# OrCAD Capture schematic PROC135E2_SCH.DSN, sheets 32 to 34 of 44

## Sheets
32 32. USER EXPANSION CONNECTOR: size C; title: USER EXPANSION CONNECTOR
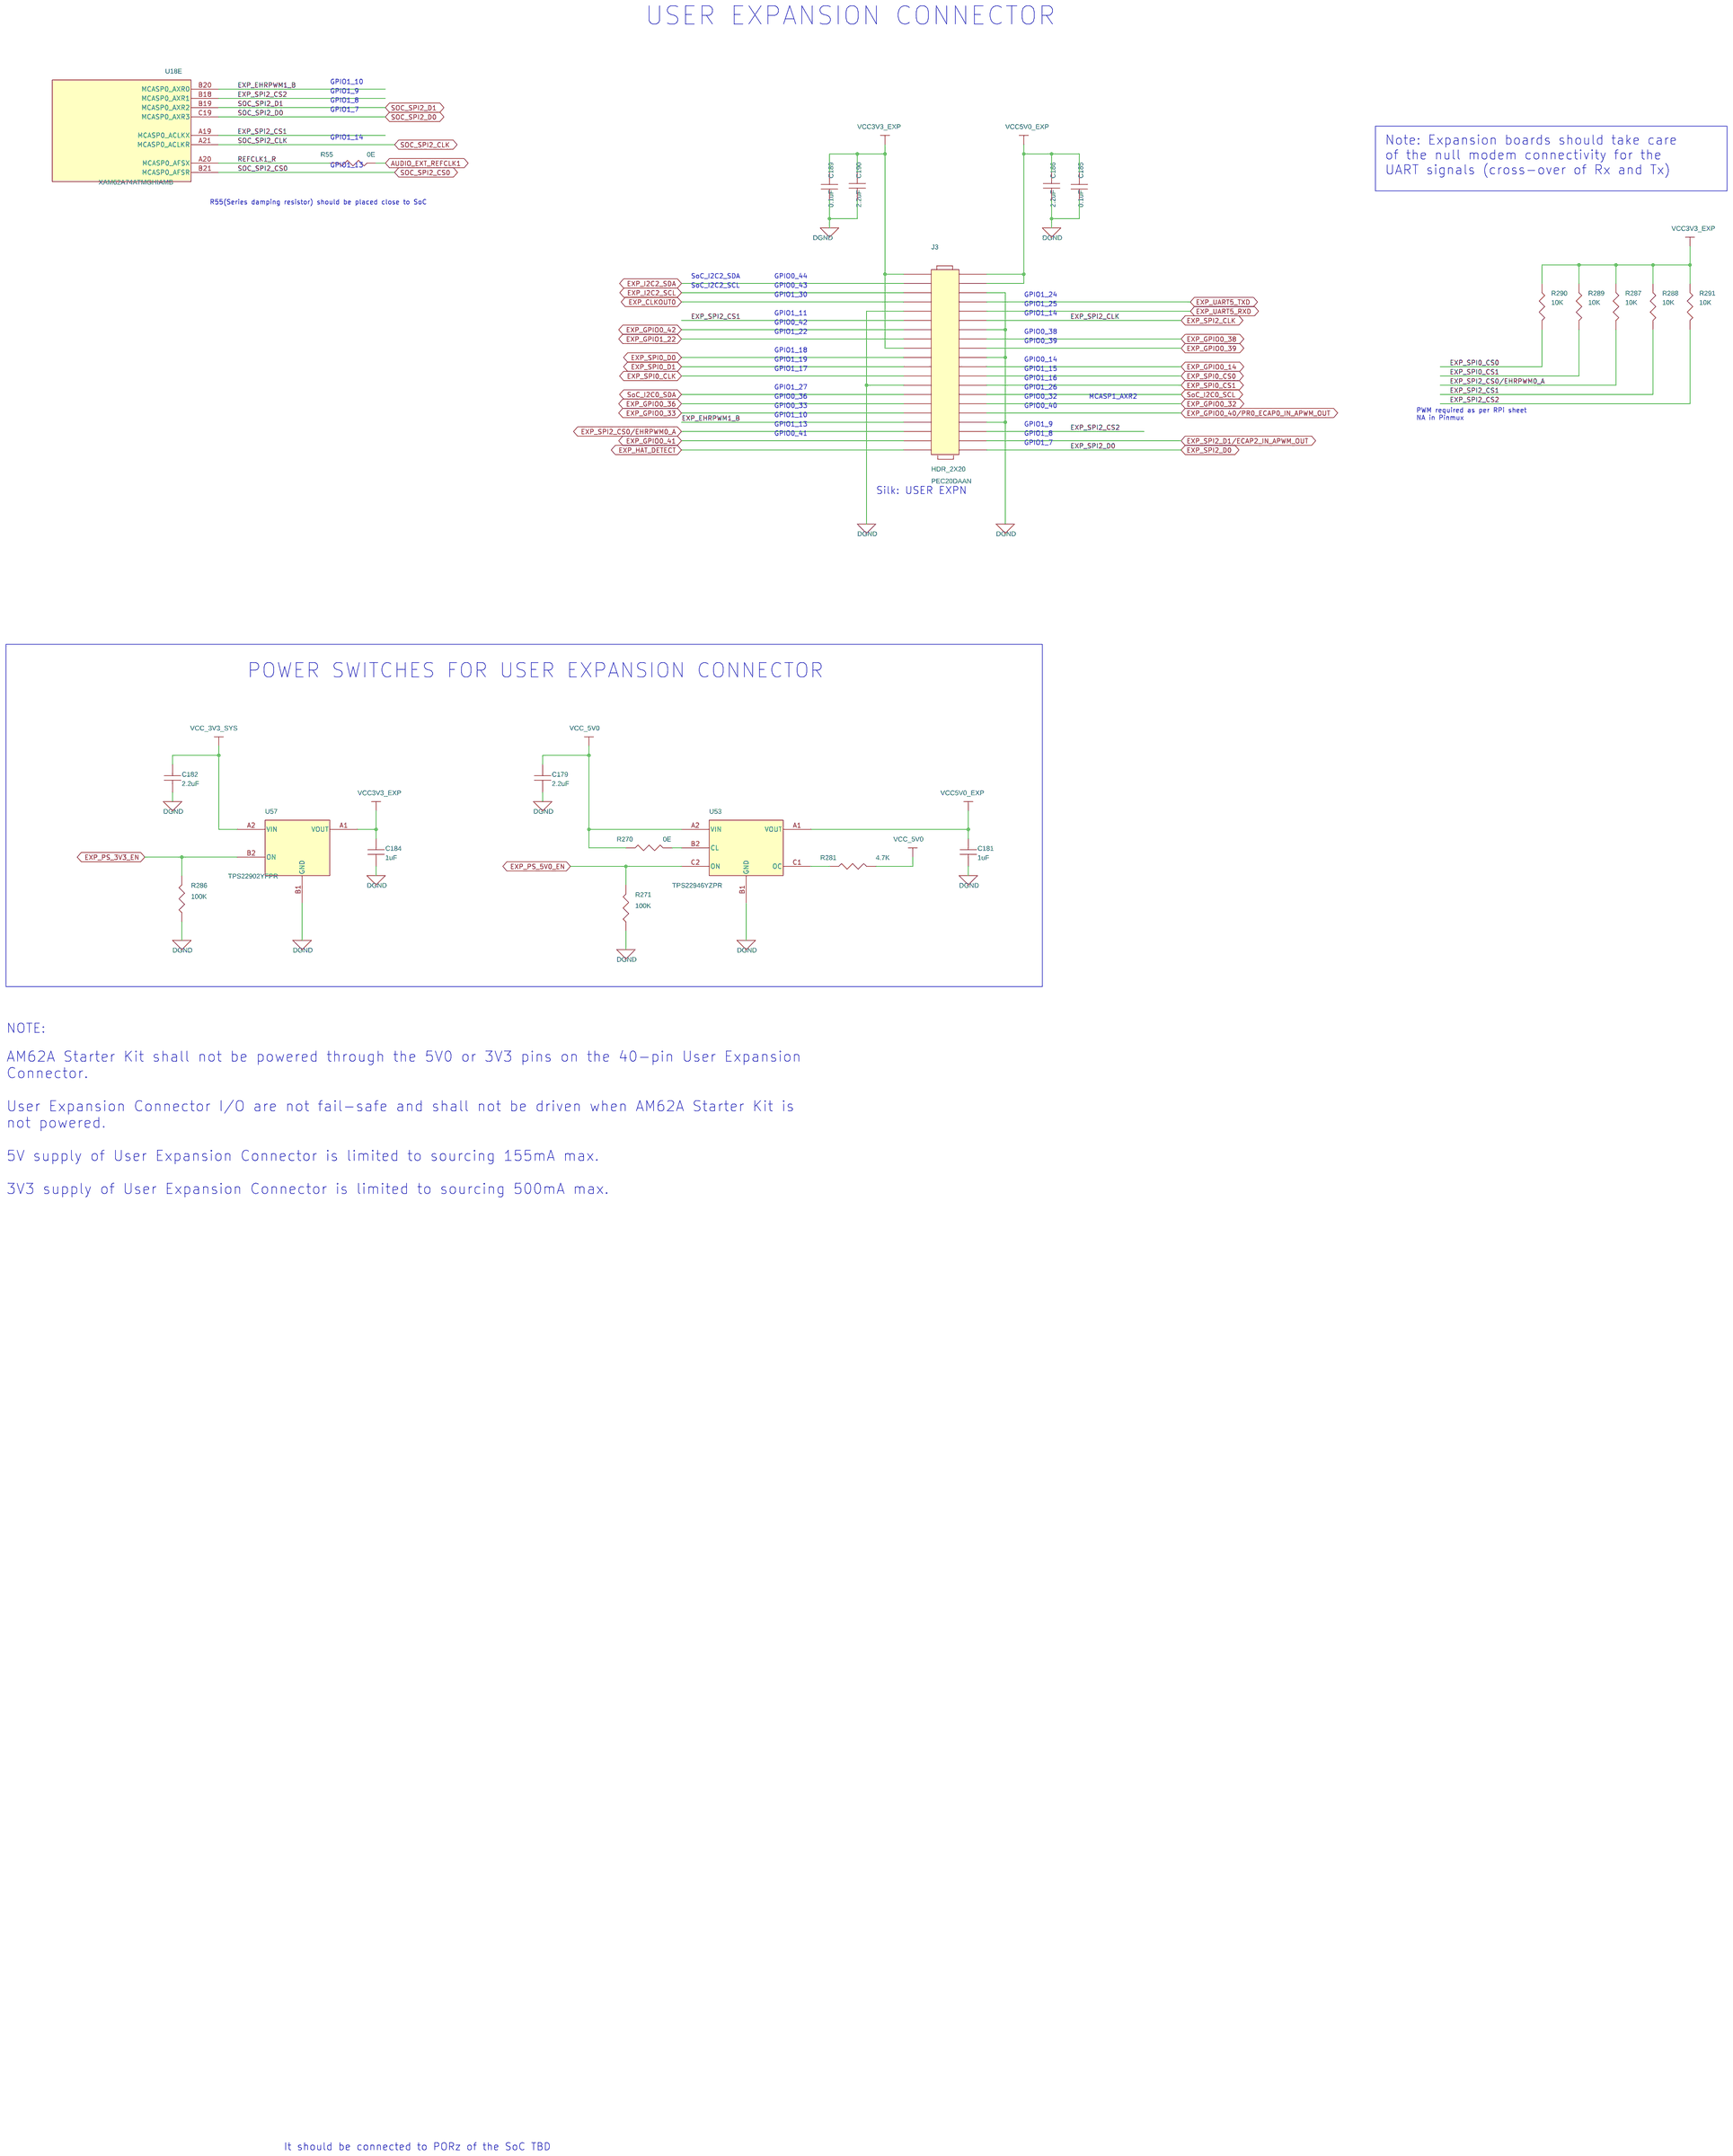
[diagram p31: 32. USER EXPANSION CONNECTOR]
33 33. MCU HEADER: size C; title: MCU HEADER
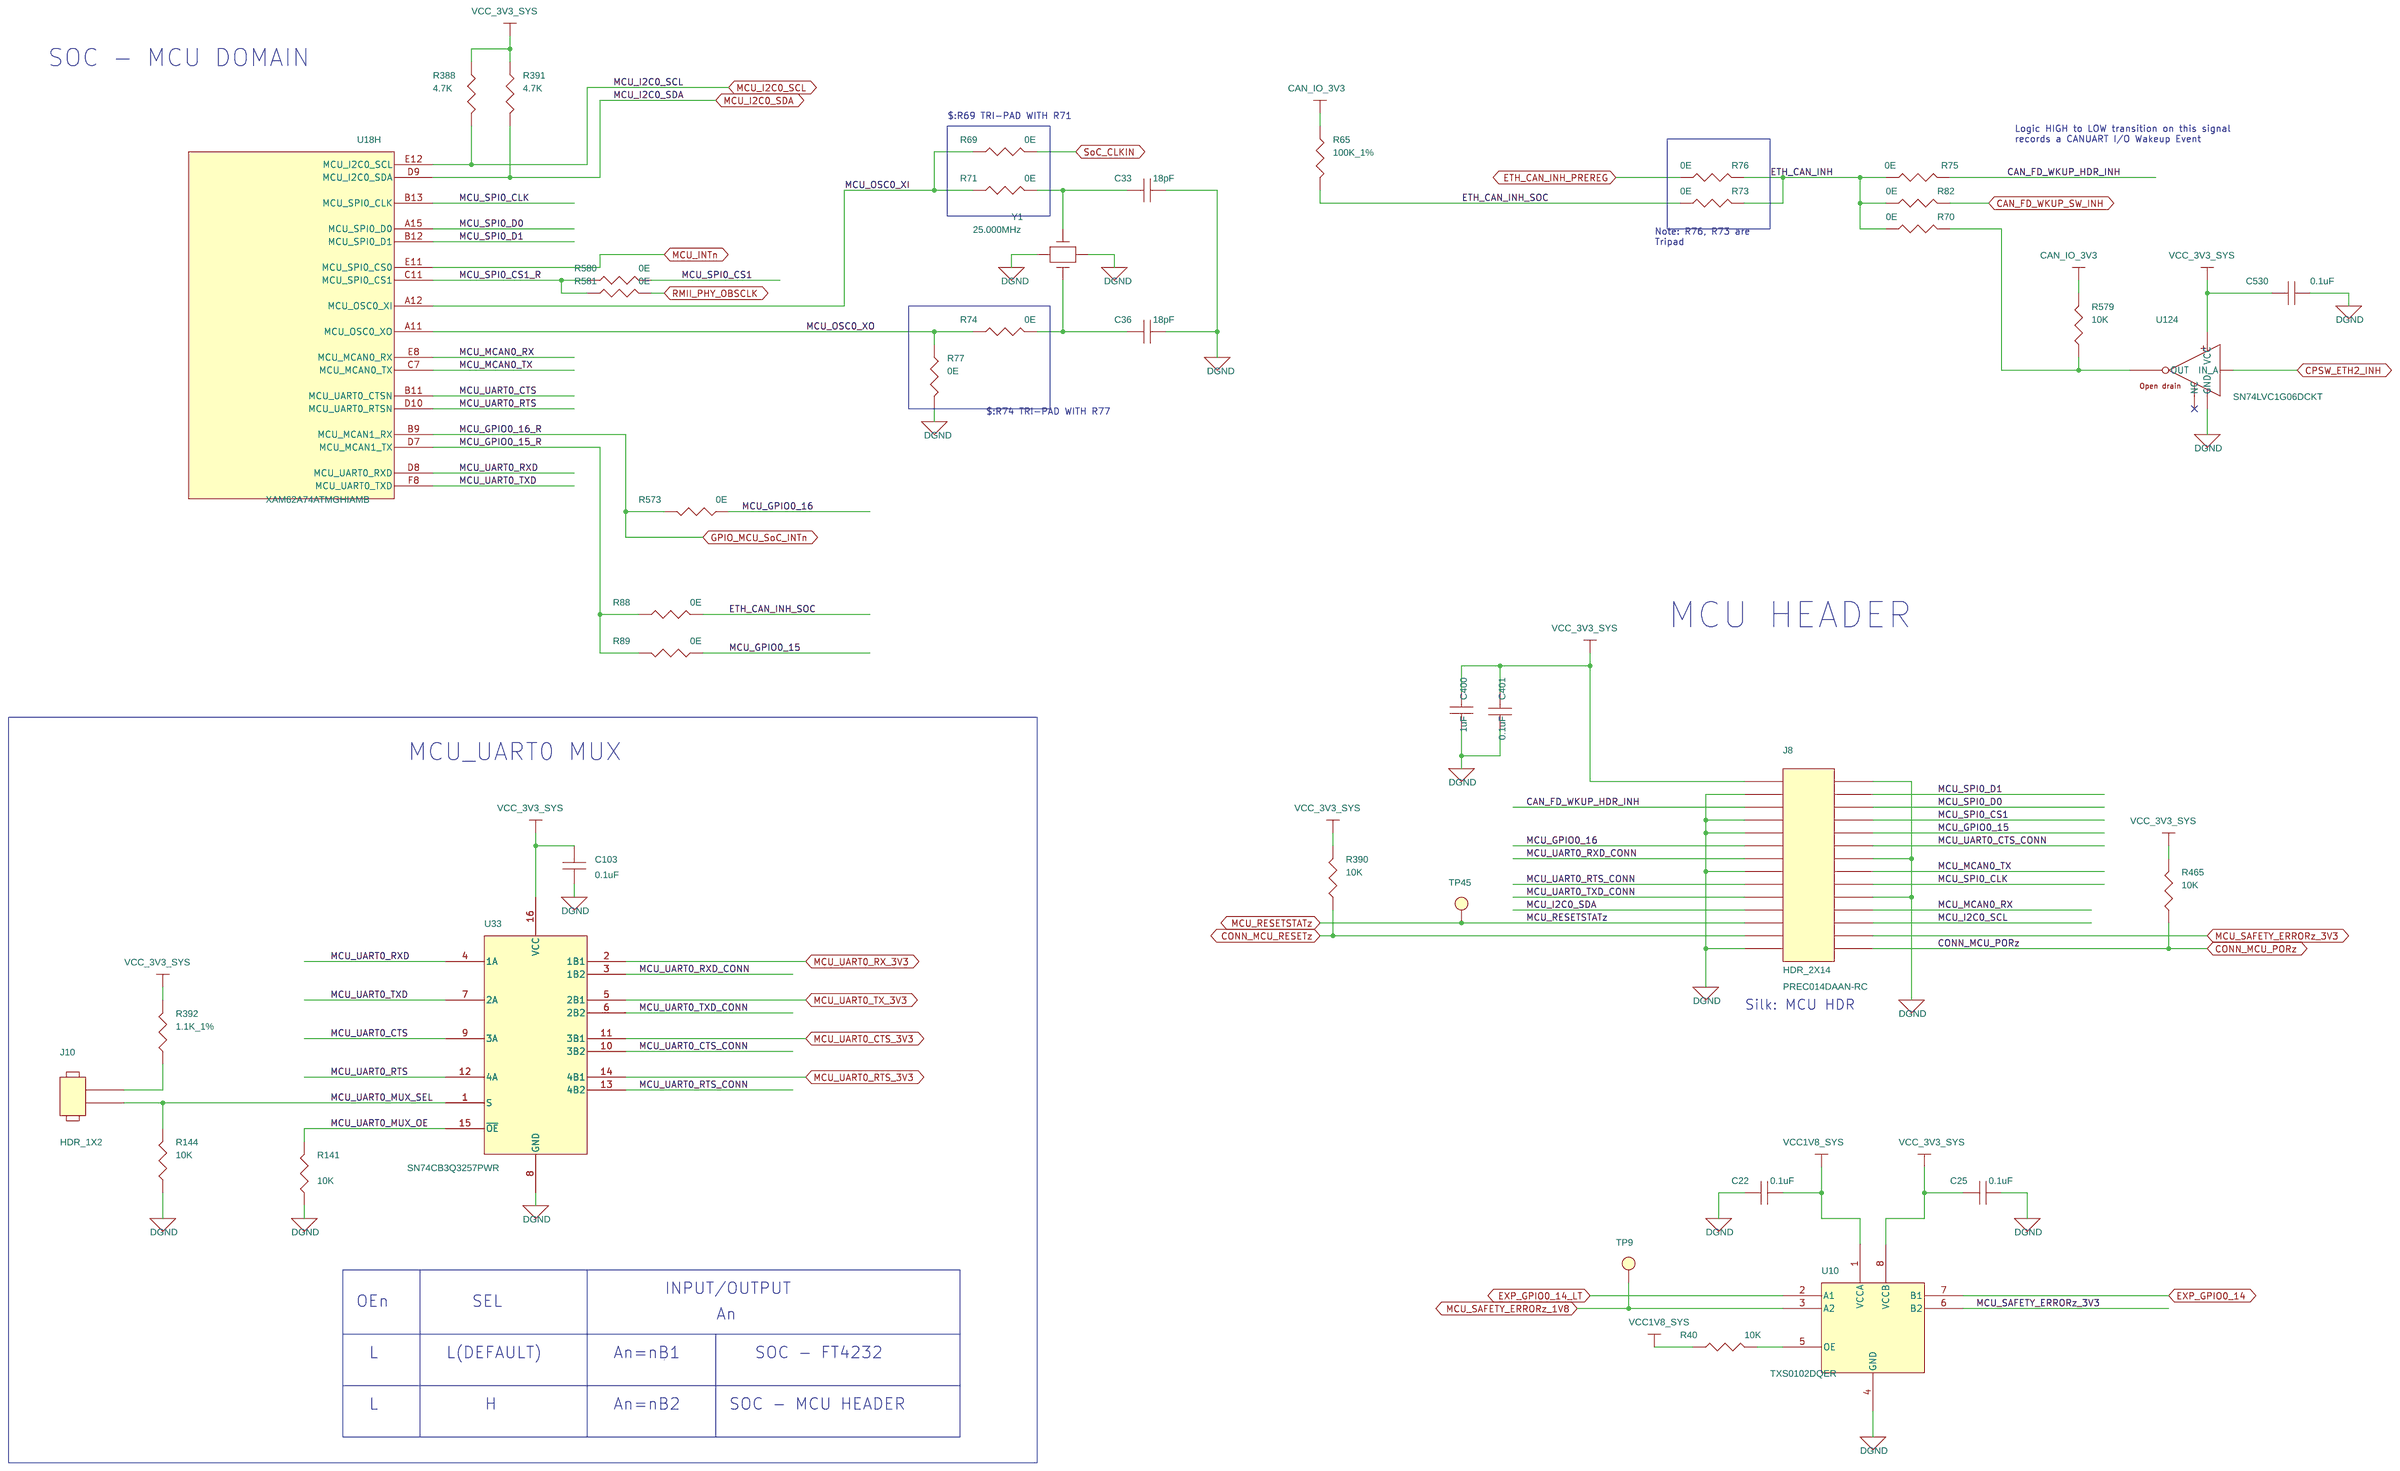
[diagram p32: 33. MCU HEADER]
34 34. USB1 TYPE-A: size C; title: USB1 TYPE-A
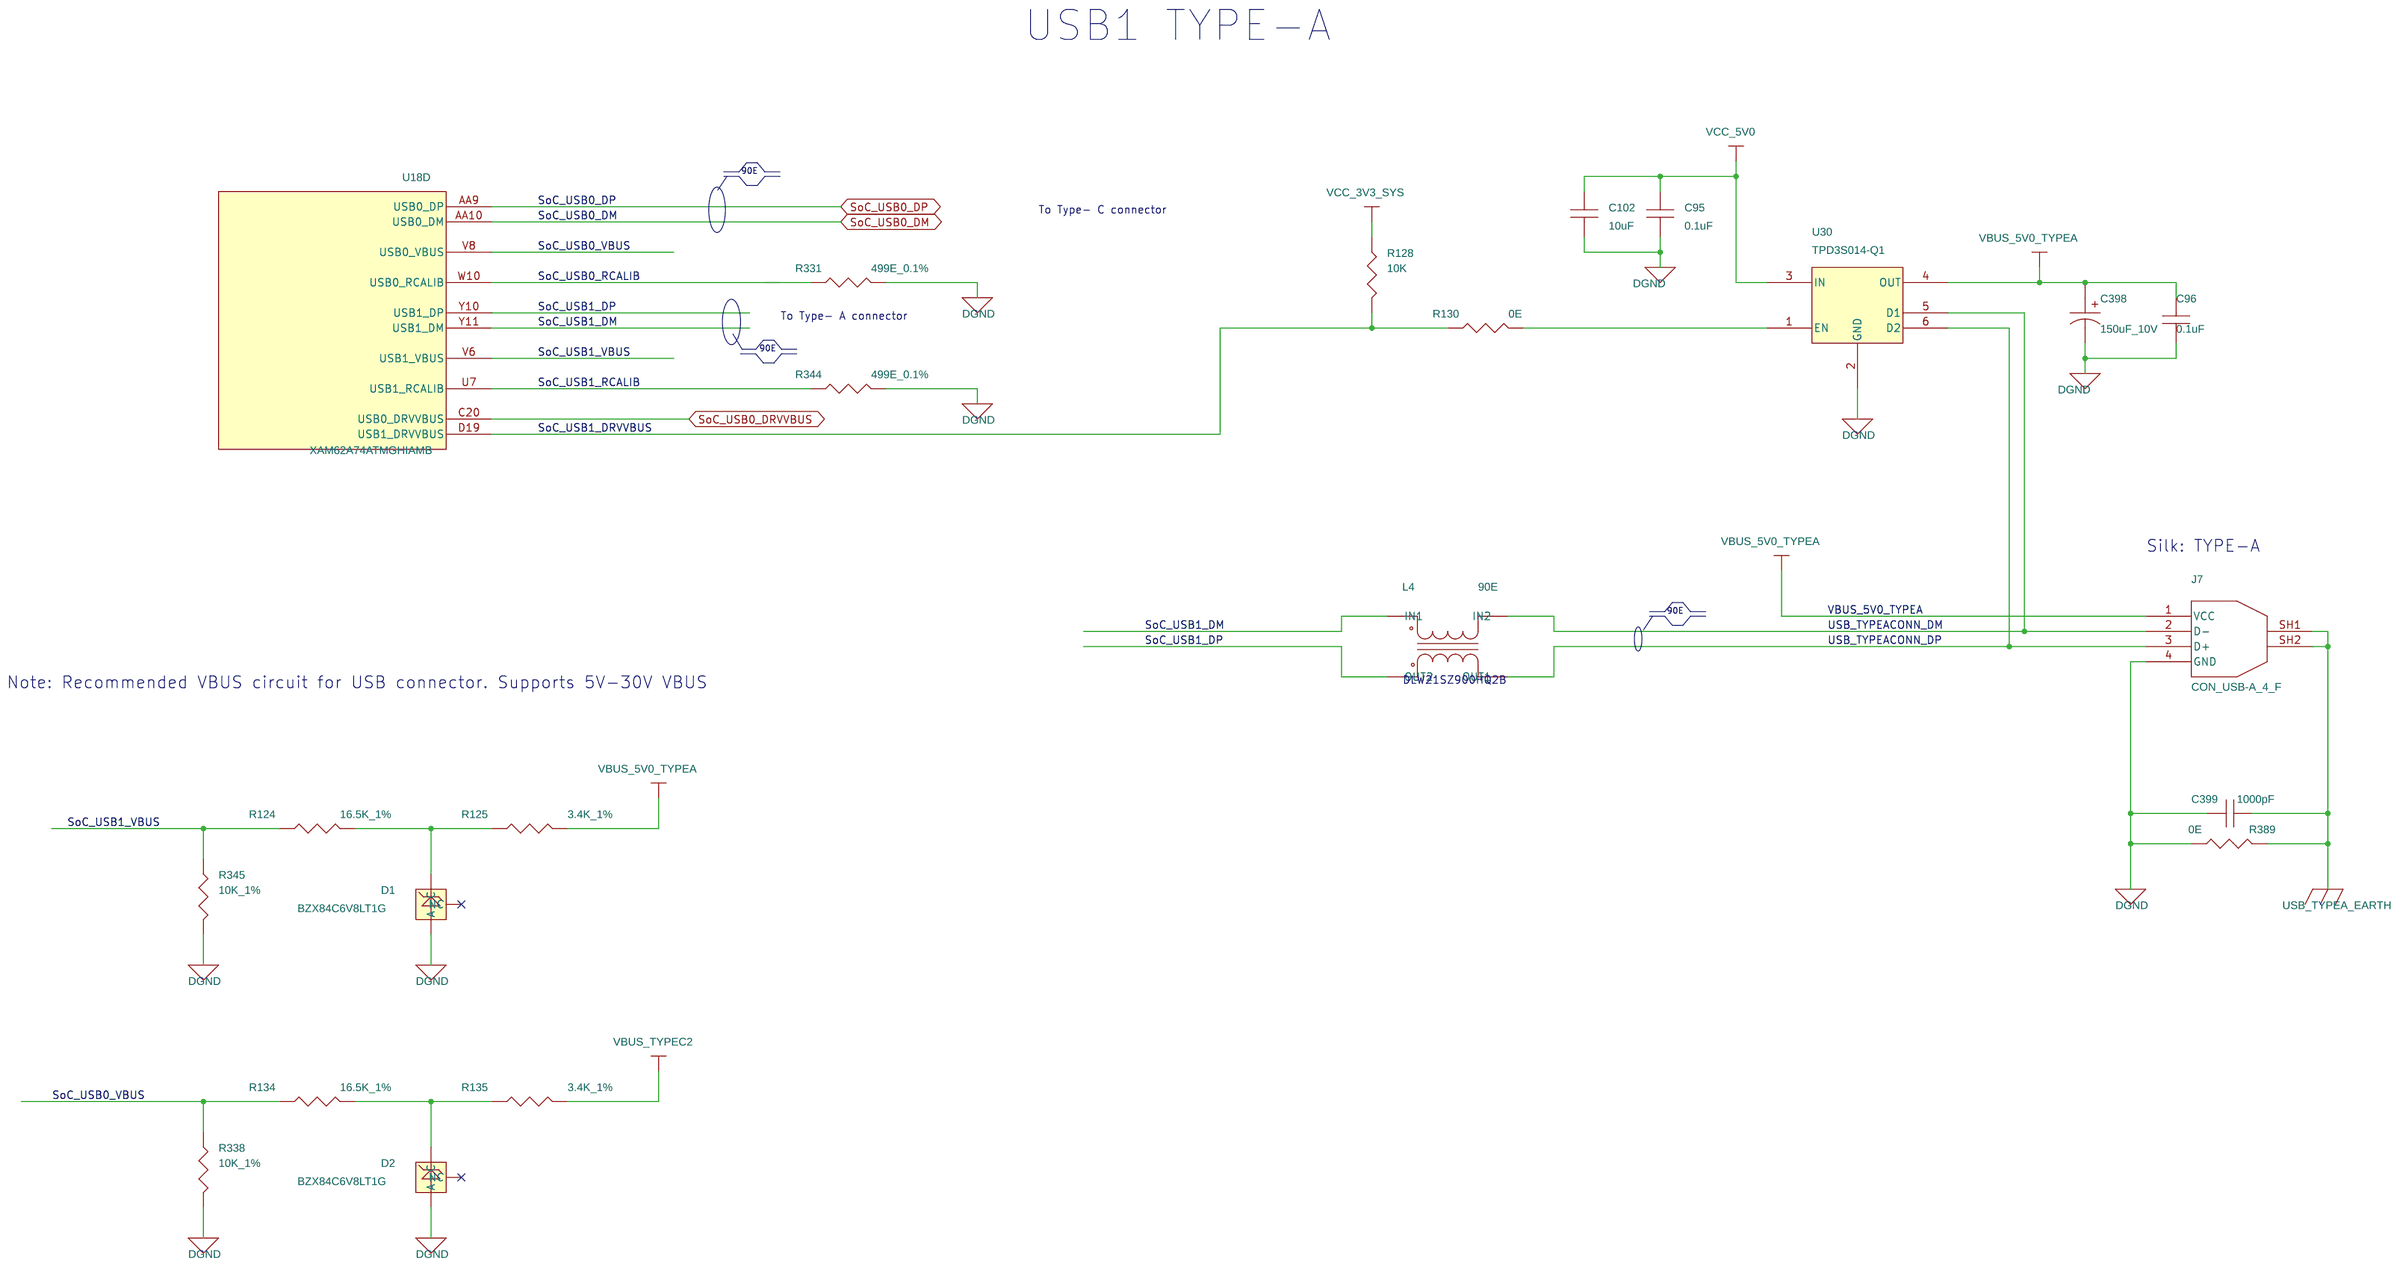
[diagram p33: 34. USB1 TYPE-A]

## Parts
sheet 31. SOC WKUP & GPMC
U18  XAM62A74ATMGHIAMB  [FBGA484_31-49_710X710_2-7]  (sections A,B,C,D,E,F,G,H,I,J,K,L,M,N,O,P,Q)
sheet 32. USER EXPANSION CONNECTOR
C179  2.2uF  [CAP0402_0-75]
C181  1uF  [CAP0201_0-5]
C182  2.2uF  [CAP0402_0-75]
C184  1uF  [CAP0201_0-5]
C185  0.1uF  [CAP0402_0-75]
C186  2.2uF  [CAP0402_0-75]
C189  0.1uF  [CAP0402_0-75]
C190  2.2uF  [CAP0402_0-75]
J3  HDR_2X20  [HDR_2X20_PEC20DAAN_S_T_8-6]
R55  0E  [RES0201_0-5]
R270  0E  [RES0201_0-5]
R271  100K  [RES0201_0-5]
R281  4.7K  [RES0201_0-5]
R286  100K  [RES0201_0-5]
R287  10K  [RES0201_0-5]
R288  10K  [RES0201_0-5]
R289  10K  [RES0201_0-5]
R290  10K  [RES0201_0-5]
R291  10K  [RES0201_0-5]
U53  TPS22946YZPR  [DSBGA6_19-68_40X60_0-5]
U57  TPS22902YFPR  [DSBGA4_15-74_30X30_0-5]
sheet 33. MCU HEADER
C22  0.1uF  [CAP0201_0-5]
C25  0.1uF  [CAP0201_0-5]
C33  18pF  [CAP0402_0-75]
C36  18pF  [CAP0402_0-75]
C103  0.1uF  [CAP0402_0-75]
C400  1uF  [CAP0201_0-5]
C401  0.1uF  [CAP0402_0-75]
C530  0.1uF  [CAP0402_0-75]
J8  HDR_2X14  [HDR_14X2_100_S_T]
J10  HDR_1X2  [HDR_1X2_90120-0122_S_T_5-6]
R40  10K  [RES0201_0-5]
R65  100K_1%  [RES0402_0-5]
R69  0E  [RES0201_0-5]
R70  0E  [RES0201_0-5]
R71  0E  [RES0201_0-5]
R73  0E  [RES0201_0-5]
R74  0E  [RES0201_0-5]
R75  0E  [RES0201_0-5]
R76  0E  [RES0201_0-5]
R77  0E  [RES0201_0-5]
R82  0E  [RES0201_0-5]
R88  0E  [RES0201_0-5]
R89  0E  [RES0201_0-5]
R141  10K  [RES0201_0-5]
R144  10K  [RES0201_0-5]
R388  4.7K  [RES0201_0-5]
R390  10K  [RES0201_0-5]
R391  4.7K  [RES0201_0-5]
R392  1.1K_1%  [RES0201_0-5]
R465  10K  [RES0201_0-5]
R573  0E  [RES0201_0-5]
R579  10K  [RES0201_0-5]
R580  0E  [RES0201_0-5]
R581  0E  [RES0201_0-5]
TP9  TP20_SMD  [TP20_SMD]
TP45  TP20_SMD  [TP20_SMD]
U10  TXS0102DQER  [X2SON8_TXS0102_40X60_0-4]
U33  SN74CB3Q3257PWR  [TSSOP16_25-59_205X180]
U124  SN74LVC1G06DCKT  [SC70-5_1-1]
Y1  25.000MHz  [XTAL4_XRCGB-FM_80X60_SMD_0-7]
sheet 34. USB1 TYPE-A
C95  0.1uF  [CAP0201_0-5]
C96  0.1uF  [CAP0201_0-5]
C102  10uF  [CAP0603_1]
C398  150uF_10V  [CAPT7343D_3-25]
C399  1000pF  [CAP1206_1-75]
D1  BZX84C6V8LT1G  [SOT23-123_1-2]
D2  BZX84C6V8LT1G  [SOT23-123_1-2]
J7  CON_USB-A_4_F  [CON_USBA4_629104151_S_R_S_7-4]
L4  90E  [IND4_DLW21H_90X60_SMD_1-4]
R124  16.5K_1%  [RES0402_0-5]
R125  3.4K_1%  [RES0201_0-5]
R128  10K  [RES0201_0-5]
R130  0E  [RES0201_0-5]
R134  16.5K_1%  [RES0402_0-5]
R135  3.4K_1%  [RES0201_0-5]
R331  499E_0.1%  [RES0402_0-5]
R338  10K_1%  [RES0201_0-5]
R344  499E_0.1%  [RES0402_0-5]
R345  10K_1%  [RES0201_0-5]
R389  0E  [RES0603_0-75]
U30  TPD3S014-Q1  [SOT23-6_1-5]

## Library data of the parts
U18 = AM62A-EVM_SOC_FCBGA484: IC AM62A SK EVM SoC MICROPROCESSOR FCBGA484; Chkd/date: PRAVEEN/190922; Crtd /date: PRAVEEN/190922; Custom_Duty: 15%; Customs_HS_Code: 85423100; Distributor_name: NA; Distributor_part_number: NA; Footprint Path: Y:\MIS_DATABASE\Library\ALTIUM_TOOL\PCB_FOOTPRINTS\Altium_Footprint_Lib.PcbLib; Height: 2.65MM; Library Ref: AM62A-EVM_SoC_FCBGA484; Mfr_name: TEXAS INSTRUMENTS; Mistral Part No: 141220090002; Package: FCBGA484; Part_type: ICS\DIGITAL\MICROPROCESSOR; Project: TI_AM62A_SK_EVM; RoHS: NA; Temperature: NA; Tolerance: NA; Voltage: NA; Wattage: NA; Weight: NA; Datasheet: Y:\MIS_DATABASE\DATASHEETS\ICS\DIGITAL\MICROCONTROLLER\AM62A_SK_EVM.PDF
C179 C182 C186 C190 = CAP: CAP CERAMIC 2.2uF 25V 10% X5R 0402; Chkd/date: ALVY/010721; Crtd /date: MANIRAJA/010721; Custom_Duty: 15%; Customs_HS_Code: 85322990; Distributor_name: DIGIKEY; Distributor_part_number: 490-12703-1-ND; Footprint Path: Y:\MIS_DATABASE\Library\ALTIUM_TOOL\PCB_FOOTPRINTS\Altium_Footprint_Lib.PcbLib; Height: 0.70MM; Library Path: Y:\MIS_DATABASE\Library\ALTIUM_TOOL\SCHEMATICS_PARTS\MS_DISCRETE_Library.schlib; Mfr_name: MURATA; Mfr_part_number: GRM155R61E225KE11D; Mistral Part No: 120015120001-R; Package: 0402; Part_type: CAPACITORS\CERAMIC; Project: TI_AM263X_CC; RoHS: RoHS; Temperature: -55°C+85°C; Tolerance: 10%; Voltage: 25V; Wattage: NA; Weight: 1.5mg; Datasheet: Y:\MIS_DATABASE\DATASHEETS\CAPACITORS\GRM155R61E225KE11.PDF
C181 C184 C400 = CAP: CAP CERAMIC 1uF 16V 20% X5R 0201; Chkd/date: MANIRAJA/300520; Crtd /date: ALVY/260520; Custom_Duty: 15%; Customs_HS_Code: 85322990; Distributor_name: DIGIKEY; Distributor_part_number: 490-18654-1-ND; Footprint Path: Y:\MIS_DATABASE\Library\ALTIUM_TOOL\PCB_FOOTPRINTS\Altium_Footprint_Lib.PcbLib; Height: 0.39MM; Library Path: Y:\MIS_DATABASE\Library\ALTIUM_TOOL\SCHEMATICS_PARTS\MS_DISCRETE_Library.schlib; Mfr_name: MURATA; Mfr_part_number: GRM033R61C105ME15D; Mistral Part No: 120018090038-R; Package: 0201; Part_type: CAPACITORS\CERAMIC; Project: QCS610_NANOSOM; RoHS: RoHS; Temperature: -55°C+85°C; Tolerance: 20%; Voltage: 16V; Wattage: NA; Weight: 0.33mg; Datasheet: Y:\MIS_DATABASE\DATASHEETS\CAPACITORS\GRM033R61C105ME15.PDF
C103 C185 C189 C401 C530 = CAP: CAP CERAMIC 0.1uF 50V 10% X7R 0402; Alt_Mfr_name: YAGEO AMERICA; Alt_Mfr_part_number: CC0402KRX5R8BB104; Chkd/date: MANIRAJA/261020; Crtd /date: ALVY/211020; Custom_Duty: 15%; Customs_HS_Code: 85322990; Distributor_name: DIGIKEY; Distributor_part_number: 490-10700-1-ND; Footprint Path: Y:\MIS_DATABASE\Library\ALTIUM_TOOL\PCB_FOOTPRINTS\Altium_Footprint_Lib.PcbLib; Height: 0.55MM; Library Path: Y:\MIS_DATABASE\Library\ALTIUM_TOOL\SCHEMATICS_PARTS\MS_DISCRETE_Library.schlib; Mfr_name: MURATA; Mfr_part_number: GRM155R71H104KE14D; Mistral Part No: 120011100014-R; Package: 0402; Part_type: CAPACITORS\CERAMIC; Project: J7_CP; RoHS: RoHS; Temperature: -55°C+125°C; Tolerance: 10%; Voltage: 50V; Wattage: NA; Weight: 3.1mg; Datasheet: Y:\MIS_DATABASE\DATASHEETS\CAPACITORS\GRM155R71H104KE14.PDF
J3 = HEADER_20X2: CON HDR 2X20 2.54MM PITCH ST TH; Chkd/date: MANIRAJA/261020; Crtd /date: MANIRAJA/261020; Custom_Duty: 24%; Customs_HS_Code: 85369090; Distributor_name: DIGIKEY; Distributor_part_number: S2012E-20-ND; Footprint Path: Y:\MIS_DATABASE\Library\ALTIUM_TOOL\PCB_FOOTPRINTS\Altium_Footprint_Lib.PcbLib; Height: 8.58MM; Library Path: Y:\MIS_DATABASE\Library\ALTIUM_TOOL\SCHEMATICS_PARTS\MS_CONNECTOR_Library.schlib; Mfr_name: SULLINS CONNECTOR; Mfr_part_number: PEC20DAAN; Mistral Part No: 150020100013-R; Package: THRU-HOLE; Part_type: CONNECTOR\HEADERS; Project: AM64X_SKEVM; RoHS: RoHS; Temperature: -65°C+125°C; Tolerance: NA; Voltage: NA; Wattage: NA; Weight: NA; Datasheet: Y:\MIS_DATABASE\DATASHEETS\CONNECTORS\XXCXXDXXN.PDF
R55 R69-R71 R73-R75 R77 R88 R89 R130 R270 R573 R580 R581 = RESISTOR: RES 0E 1/20W 5% 0201; Chkd/date: NAVEED/301214; Crtd /date: MUDDU/120710; Custom_Duty: 15%; Customs_HS_Code: 85332119; Distributor_name: DIGIKEY; Distributor_part_number: 311-0.0NCT-ND; Footprint Path: Y:\MIS_DATABASE\Library\ALTIUM_TOOL\PCB_FOOTPRINTS\Altium_Footprint_Lib.PcbLib; Height: 0.26MM; Library Path: Y:\MIS_DATABASE\Library\ALTIUM_TOOL\SCHEMATICS_PARTS\MS_DISCRETE_Library.schlib; Mfr_name: YAGEO AMERICA; Mfr_part_number: RC0201JR-070RL; Mistral Part No: 110010070067-R; Package: 0201; Part_type: RESISTORS\FIXED; Project: PB_BUGBASE; RoHS: RoHS; Temperature: -55°C+125°C; Tolerance: 5%; Voltage: NA; Wattage: 1/20W; Weight: 0.17mg; Datasheet: Y:\MIS_DATABASE\DATASHEETS\RESISTORS\RCXXXXL-SER_MAR18.PDF
R271 R286 = RESISTOR: RES 100K 1/20W 5% 0201; Chkd/date: MANIRAJA/050517; Crtd /date: MANIRAJA/050517; Custom_Duty: 15%; Customs_HS_Code: 85332119; Distributor_name: DIGIKEY; Distributor_part_number: 311-100KNCT-ND; Footprint Path: Y:\MIS_DATABASE\Library\ALTIUM_TOOL\PCB_FOOTPRINTS\Altium_Footprint_Lib.PcbLib; Height: 0.26MM; Library Path: Y:\MIS_DATABASE\Library\ALTIUM_TOOL\SCHEMATICS_PARTS\MS_DISCRETE_Library.schlib; Mfr_name: YAGEO AMERICA; Mfr_part_number: RC0201JR-07100KL; Mistral Part No: 110009030176-R; Package: 0201; Part_type: RESISTORS\FIXED; Project: GOLDEN-I LITE; RoHS: RoHS; Temperature: -55°C+125°C; Tolerance: 5%; Voltage: NA; Wattage: 1/20W; Weight: 0.17mg; Datasheet: Y:\MIS_DATABASE\DATASHEETS\RESISTORS\RCXXXXL-SER_MAR18.PDF
R281 R388 R391 = RESISTOR: RES 4.7K 1/20W 5% 0201; Chkd/date: MANIRAJA/200921; Crtd /date: ALVY/200921; Custom_Duty: 15%; Customs_HS_Code: 85332119; Distributor_name: DIGIKEY; Distributor_part_number: 311-4.7KNCT-ND; Footprint Path: Y:\MIS_DATABASE\Library\ALTIUM_TOOL\PCB_FOOTPRINTS\Altium_Footprint_Lib.PcbLib; Height: 0.26MM; Library Path: Y:\MIS_DATABASE\Library\ALTIUM_TOOL\SCHEMATICS_PARTS\MS_DISCRETE_Library.schlib; Mfr_name: YAGEO AMERICA; Mfr_part_number: RC0201JR-074K7L; Mistral Part No: 110021090007-R; Package: 0201; Part_type: RESISTORS\FIXED; Project: TI_AM62x SKEVM_BRD; RoHS: RoHS; Temperature: -55°C+125°C; Tolerance: 5%; Voltage: NA; Wattage: 1/20W; Weight: 0.17mg; Datasheet: Y:\MIS_DATABASE\DATASHEETS\RESISTORS\RCXXXXL-SER_MAR18.PDF
R40 R128 R141 R144 R287-R291 R390 R465 R579 = RESISTOR: RES 10K 1/20W 5% 0201; Chkd/date: MANIRAJA/050517; Crtd /date: MANIRAJA/050517; Custom_Duty: 15%; Customs_HS_Code: 85332119; Distributor_name: DIGIKEY; Distributor_part_number: 311-10KNCT-ND; Footprint Path: Y:\MIS_DATABASE\Library\ALTIUM_TOOL\PCB_FOOTPRINTS\Altium_Footprint_Lib.PcbLib; Height: 0.26MM; Library Path: Y:\MIS_DATABASE\Library\ALTIUM_TOOL\SCHEMATICS_PARTS\MS_DISCRETE_Library.schlib; Mfr_name: YAGEO AMERICA; Mfr_part_number: RC0201JR-0710KL; Mistral Part No: 110010070051-R; Package: 0201; Part_type: RESISTORS\FIXED; Project: GOLDEN-I LITE; RoHS: RoHS; Temperature: -55°C+125°C; Tolerance: 5%; Voltage: NA; Wattage: 1/20W; Weight: 0.17mg; Datasheet: Y:\MIS_DATABASE\DATASHEETS\RESISTORS\RCXXXXL-SER_MAR18.PDF
U53 = TPS22946_DSBGA6: IC CURRENT-LIMITED LOAD SWITCH WITH SHUTOFF AUTO-RESTART AND OVERCURRENT CONDITION TIME-OUT DSBGA6; Chkd/date: MANIRAJA/220121; Crtd /date: ALVY/220121; Custom_Duty: 15%; Customs_HS_Code: 85423100; Distributor_name: DIGIKEY; Distributor_part_number: 296-25219-1-ND; Footprint Path: Y:\MIS_DATABASE\Library\ALTIUM_TOOL\PCB_FOOTPRINTS\Altium_Footprint_Lib.PcbLib; Height: 0.50MM; Library Path: Y:\MIS_DATABASE\Library\ALTIUM_TOOL\SCHEMATICS_PARTS\MS_MISCPOWER_Library.schlib; Mfr_name: TEXAS INSTRUMENTS; Mistral Part No: 142021010016-R; Package: DSBGA6; Part_type: ICS\POWER\MANAGEMENT; Project: AM64X_SKEVM; RoHS: RoHS; Temperature: -40°C+85°C; Tolerance: NA; Voltage: NA; Wattage: NA; Weight: 1.7mg; Datasheet: Y:\MIS_DATABASE\DATASHEETS\ICS\POWER\TPS22946.PDF
U57 = TPS22912CYZVR_DSBGA4: IC 3.6V 500mA 78mE ON-RESISTANCE LOAD SWITCH WITH CONTROLLED TURNON DSBGA4; Chkd/date: MANIRAJA/170920; Crtd /date: ALVY/160920; Custom_Duty: 15%; Customs_HS_Code: 85423100; Distributor_name: DIGIKEY; Distributor_part_number: 296-24472-1-ND; Footprint Path: Y:\MIS_DATABASE\Library\ALTIUM_TOOL\PCB_FOOTPRINTS\Altium_Footprint_Lib.PcbLib; Height: 0.50MM; Library Path: Y:\MIS_DATABASE\Library\ALTIUM_TOOL\SCHEMATICS_PARTS\MS_MISCPOWER_Library.schlib; Mfr_name: TEXAS INSTRUMENTS; Mistral Part No: 142020090007-R; Package: DSBGA4; Part_type: ICS\POWER; Project: AM64X_SKEVM; RoHS: RoHS; Temperature: -40°C+85°C; Tolerance: NA; Voltage: NA; Wattage: NA; Weight: 0.7mg; Datasheet: Y:\MIS_DATABASE\DATASHEETS\ICS\POWER\TPS22901-2-3.PDF
C22 C25 = CAP: CAP CERAMIC 0.1uF 16V 10% X5R 0201; Alt_Mfr_name: YAGEO AMERICA; Alt_Mfr_part_number: CC0402KRX5R8BB104; Chkd/date: MANIRAJA/230118; Crtd /date: MANIRAJA/230118; Custom_Duty: 15%; Customs_HS_Code: 85322990; Distributor_name: DIGIKEY; Distributor_part_number: 490-14305-1-ND; Footprint Path: Y:\MIS_DATABASE\Library\ALTIUM_TOOL\PCB_FOOTPRINTS\Altium_Footprint_Lib.PcbLib; Height: 0.33MM; Library Path: Y:\MIS_DATABASE\Library\ALTIUM_TOOL\SCHEMATICS_PARTS\MS_DISCRETE_Library.schlib; Mfr_name: MURATA; Mfr_part_number: GRM033R61C104KE14D; Mistral Part No: 120009030072-R; Package: 0201; Part_type: CAPACITORS\CERAMIC; Project: TI_MAXIE_CPB; RoHS: RoHS; Temperature: -55°C+85°C; Tolerance: 10%; Voltage: 16V; Wattage: NA; Weight: 0.33mg; Datasheet: Y:\MIS_DATABASE\DATASHEETS\CAPACITORS\GRM033R61C104KE14.PDF
C33 C36 = CAP: CAP CERAMIC 18pF 50V 5% HI-Q C0G(NP0) 0402; Chkd/date: VASANTHA/030315; Crtd /date: NAVEED/271014; Custom_Duty: 15%; Customs_HS_Code: 85322990; Distributor_name: DIGIKEY; Distributor_part_number: 490-3119-1-ND; Footprint Path: Y:\MIS_DATABASE\Library\ALTIUM_TOOL\PCB_FOOTPRINTS\Altium_Footprint_Lib.PcbLib; Height: 0.55MM; Library Path: Y:\MIS_DATABASE\Library\ALTIUM_TOOL\SCHEMATICS_PARTS\MS_DISCRETE_Library.schlib; Mfr_name: MURATA; Mfr_part_number: GJM1555C1H180JB01D; Mistral Part No: 120014100019-R; Package: 0402; Part_type: CAPACITORS\CERAMIC; Project: DC_MIST_RDC; RoHS: RoHS; Temperature: -55°C+125°C; Tolerance: 5%; Voltage: 50V; Wattage: NA; Weight: 6mg; Datasheet: Y:\MIS_DATABASE\DATASHEETS\CAPACITORS\MURATA-GXX-SER_NOV17.PDF
J8 = HEADER_14x2: CON HDR 2X14 2.54MM PITCH ST TH; Chkd/date: NAVEED/280515; Crtd /date: VASANTHA/111114; Custom_Duty: 0.24; Customs_HS_Code: 85369090; Distributor_name: DIGIKEY; Distributor_part_number: S2012EC-14-ND; Height: 8.34MM; Mfr_name: SULLINS; Mfr_part_number: PREC014DAAN-RC; Mistral Part No: 150014110005-R; Package: THRU-HOLE; Part_type: CONNECTOR\HEADERS; Project: GALILEO_EVM; RoHS: RoHS; Temperature: -40°C+105°C; Tolerance: NA; Voltage: NA; Wattage: NA; Weight: NA; Datasheet: Y:\MIS_DATABASE\DATASHEETS\CONNECTORS\PRXXXN-RC.PDF
J10 = HEADER_2X1: CON HDR 1X2 2.54MM PITCH ST TH; Chkd/date: NAVEED/210714; Crtd /date: USMAN/031012; Custom_Duty: 24%; Customs_HS_Code: 85369090; Distributor_name: DIGIKEY; Distributor_part_number: WM8072-ND; Footprint Path: Y:\MIS_DATABASE\Library\ALTIUM_TOOL\PCB_FOOTPRINTS\Altium_Footprint_Lib.PcbLib; Height: 5.60MM; Library Path: Y:\MIS_DATABASE\Library\ALTIUM_TOOL\SCHEMATICS_PARTS\MS_CONNECTOR_Library.schlib; Mfr_name: MOLEX; Mfr_part_number: 90120-0122; Mistral Part No: 150012100005-R; Package: THRU-HOLE; Part_type: CONNECTOR\HEADERS; Project: NPOL_FEP; RoHS: RoHS; Temperature: -55°C+125°C; Tolerance: NA; Voltage: NA; Wattage: NA; Weight: 122mg; Datasheet: Y:\MIS_DATABASE\DATASHEETS\CONNECTORS\90120-XX.PDF
R65 = RESISTOR: RES 100K 1/10W 1% 0402; Chkd/date: VASANTHA/201216; Crtd /date: MAZHAR/130306; Custom_Duty: 15%; Customs_HS_Code: 85332119; Distributor_name: DIGIKEY; Distributor_part_number: P100KLCT-ND; Footprint Path: Y:\MIS_DATABASE\Library\ALTIUM_TOOL\PCB_FOOTPRINTS\Altium_Footprint_Lib.PcbLib; Height: 0.40MM; Library Path: Y:\MIS_DATABASE\Library\ALTIUM_TOOL\SCHEMATICS_PARTS\MS_DISCRETE_Library.schlib; Mfr_name: PANASONIC-ECG; Mfr_part_number: ERJ-2RKF1003X; Mistral Part No: 110009030187-R; Package: 0402; Part_type: RESISTORS\FIXED; Project: J32; RoHS: RoHS; Temperature: -55°C+155°C; Tolerance: 1%; Voltage: NA; Wattage: 1/10W; Weight: 0.8mg; Datasheet: Y:\MIS_DATABASE\DATASHEETS\RESISTORS\PAN-ERJSER_NOV17.PDF
R76 R82 = RESISTOR: RES 0E 1/20W 5% 0201; Chkd/date: NAVEED/301214; Crtd /date: MUDDU/120710; Custom_Duty: 15%; Customs_HS_Code: 85332119; Distributor_name: DIGIKEY; Distributor_part_number: 311-0.0NCT-ND; Footprint Path: Y:\MIS_DATABASE\Library\ALTIUM_TOOL\PCB_FOOTPRINTS\Altium_Footprint_Lib.PcbLib; Height: 0.26MM; Library Path: Y:\MIS_DATABASE\Library\ALTIUM_TOOL\SCHEMATICS_PARTS\MS_DISCRETE_Library.schlib; Manufacturer: YAGEO AMERICA; Mfr_name: YAGEO AMERICA; Mfr_part_number: RC0201JR-070RL; Mistral Part No: 110010070067-R; Package: 0201; Part_type: RESISTORS\FIXED; Project: PB_BUGBASE; RoHS: RoHS; Temperature: -55°C+125°C; Tolerance: 5%; Voltage: NA; Wattage: 1/20W; Weight: 0.17mg; Datasheet: Y:\MIS_DATABASE\DATASHEETS\RESISTORS\RCXXXXL-SER_MAR18.PDF
R392 = RESISTOR: RES 1.1K 1/20W 1% 0201; Chkd/date: MANIRAJA/270721; Crtd /date: ALVY/260721; Custom_Duty: 15%; Customs_HS_Code: 85332119; Distributor_name: DIGIKEY; Distributor_part_number: YAG2474CT-ND; Footprint Path: Y:\MIS_DATABASE\Library\ALTIUM_TOOL\PCB_FOOTPRINTS\Altium_Footprint_Lib.PcbLib; Height: 0.26MM; Library Path: Y:\MIS_DATABASE\Library\ALTIUM_TOOL\SCHEMATICS_PARTS\MS_DISCRETE_Library.schlib; Mfr_name: YAGEO AMERICA; Mfr_part_number: RC0201FR-071K1L; Mistral Part No: 110009030097-R; Package: 0201; Part_type: RESISTORS\FIXED; Project: TI_AM335x SK_BRD; RoHS: RoHS; Temperature: -55°C+125°C; Tolerance: 1%; Voltage: NA; Wattage: 1/20W; Weight: 0.17mg; Datasheet: Y:\MIS_DATABASE\DATASHEETS\RESISTORS\RCXXXXL-SER_MAR18.PDF
TP9 TP45 = TESTPOINT: TESTPOINT CIR 20 SMD; Chkd/date: SHREESHAIL/171006; Crtd /date: MAZHAR/171006; Custom_Duty: NA; Customs_HS_Code: NA; Distributor_name: NA; Distributor_part_number: NA; Footprint Path: Y:\MIS_DATABASE\Library\ALTIUM_TOOL\PCB_FOOTPRINTS\Altium_Footprint_Lib.PcbLib; Height: NA; Library Path: Y:\MIS_DATABASE\Library\ALTIUM_TOOL\SCHEMATICS_PARTS\MS_DISCRETE_Library.schlib; MECHANICAL 3D STEP FILE: NA; Mfr_name: LOCAL; Mistral Part No: NA; Package: SMD; Project: BT MODULE_CSRBC04; RoHS: NA; Temperature: NA; Tolerance: NA; Voltage: NA; Wattage: NA; Weight: NA; Datasheet: NA
U10 = TXS0102DQX_SON8: IC 2-BIT BI-DIR VOLTAGE-LEVEL TRANSLATOR FOR OPEN-DRAIN AND PUSH-PULL X2SON8; Chkd/date: MANIRAJA/010719; Crtd /date: CHAITHANYA230512; Custom_Duty: 15%; Customs_HS_Code: 85423100; Distributor_name: DIGIKEY; Distributor_part_number: 296-28368-1-ND; Footprint Path: Y:\MIS_DATABASE\Library\ALTIUM_TOOL\PCB_FOOTPRINTS\Altium_Footprint_Lib.PcbLib; Height: 0.40MM; Library Path: Y:\MIS_DATABASE\Library\ALTIUM_TOOL\SCHEMATICS_PARTS\MS_MISCINTERFACE_Library.schlib; Mfr_name: TEXAS INSTRUMENTS; Mistral Part No: 141012050010-R; Package: X2SON8; Part_type: ICS\INTERFACE\LEVEL TRANSLATOR; Project: GEN_3-8_DB; RoHS: RoHS; Temperature: -40°C+85°C; Tolerance: NA; Voltage: NA; Wattage: NA; Weight: 1.2mg; Datasheet: Y:\MIS_DATABASE\DATASHEETS\ICS\INTERFACE\TXS0102-SER.PDF
U33 = SN74CB3Q3257PWR_TSSOP16: IC 4BIT 1-OF-2 FET MULTIPLEXER/DEMULTIPLEXER TSSOP16; Chkd/date: SUHAS/251010; Crtd /date: USMAN/060109; Custom_Duty: 15%; Customs_HS_Code: 85423100; Distributor_name: DIGIKEY; Distributor_part_number: 296-19138-1-ND; Height: 1.20MM; Mfr_name: TEXAS INSTRUMENTS; Mistral Part No: 141009030117-R; Package: TSSOP16; Part_type: ICS\DIGITAL\COMBINATIONAL; Project: OMAP_EVM; RoHS: Sb/ Br FREE; Temperature: -40°C+85°C; Datasheet: Y:\MIS_DATABASE\DATASHEETS\ICS\DIGITAL\COMBINATIONAL\SN74CB3Q3257.PDF
U124 = SN74LVC1G06DCKT_SC70-5_0: IC SINGLE INVERTER BUFFER/DRIVER WITH OPEN-DRAIN OUTPUT SC70-5; Chkd/date: VASANTHA/280616; Crtd /date: MAZHAR/170107; Custom_Duty: 15%; Customs_HS_Code: 85423100; Distributor_name: DIGIKEY; Distributor_part_number: 296-32290-1-ND; Footprint Path: Y:\MIS_DATABASE\Library\ALTIUM_TOOL\PCB_FOOTPRINTS\Altium_Footprint_Lib.PcbLib; Height: 1.10MM; Junction to Board °C/W: 70.9; Junction to Case °C/W: 178.9; Library Path: Y:\MIS_DATABASE\Library\ALTIUM_TOOL\SCHEMATICS_PARTS\MS_COMBINATIONAL_Library.schlib; Library Ref: SN74LVC1G06DCKT_SC70-5; Mfr_name: TEXAS INSTRUMENTS; Mistral Part No: 141009030132-R; Package: SC70-5; Part_type: ICS\DIGITAL\COMBINATIONAL; Project: OMAP2430_OSK; RoHS: RoHS; Temperature: -40°C+125°C; Tolerance: NA; Voltage: NA; Wattage: NA; Weight: 20mg; Datasheet: Y:\MIS_DATABASE\DATASHEETS\ICS\DIGITAL\COMBINATIONAL\SN74LVC1G06-SER.PDF
Y1 = CRY4_13: CRY 25.000MHz 6pF SMD; Chkd/date: MANIRAJA/151020; Crtd /date: ALVY/151020; Custom_Duty: 24%; Customs_HS_Code: 85439000; Distributor_name: DIGIKEY; Distributor_part_number: 490-5578-1-ND; Footprint Path: Y:\MIS_DATABASE\Library\ALTIUM_TOOL\PCB_FOOTPRINTS\Altium_Footprint_Lib.PcbLib; Height: 0.70MM; Library Path: Y:\MIS_DATABASE\Library\ALTIUM_TOOL\SCHEMATICS_PARTS\MS_DISCRETE_Library.schlib; Mfr_name: MURATA; Mfr_part_number: XRCGB25M000F3M00R0; Mistral Part No: 130020100043-R; Package: SMD; Part_type: CRYSTAL; Project: AM64X_SKEVM; RoHS: RoHS; Temperature: -30°C+85°C; Tolerance: NA; Voltage: NA; Wattage: NA; Weight: 23mg; Datasheet: Y:\MIS_DATABASE\DATASHEETS\MISC\CRY_OSC\XRCGB.PDF
C95 C96 = CAP: CAP CERAMIC 0.1uF 16V 10% X5R 0201; Chkd/date: MANIRAJA/230118; Crtd /date: MANIRAJA/230118; Custom_Duty: 15%; Customs_HS_Code: 85322990; Distributor_name: DIGIKEY; Distributor_part_number: 490-14305-1-ND; Footprint Path: Y:\MIS_DATABASE\Library\ALTIUM_TOOL\PCB_FOOTPRINTS\Altium_Footprint_Lib.PcbLib; Height: 0.33MM; Library Path: Y:\MIS_DATABASE\Library\ALTIUM_TOOL\SCHEMATICS_PARTS\MS_DISCRETE_Library.schlib; Mfr_name: MURATA; Mfr_part_number: GRM033R61C104KE14D; Mistral Part No: 120009030072-R; Package: 0201; Part_type: CAPACITORS\CERAMIC; Project: TI_MAXIE_CPB; RoHS: RoHS; Temperature: -55°C+85°C; Tolerance: 10%; Voltage: 16V; Wattage: NA; Weight: 0.33mg; Datasheet: Y:\MIS_DATABASE\DATASHEETS\CAPACITORS\GRM033R61C104KE14.PDF
C102 = CAP: CAP CERAMIC 10uF 35V 20% X5R 0603; Chkd/date: MANIRAJA/170519; Crtd /date: ALVY/160519; Custom_Duty: 15%; Customs_HS_Code: 85322990; Distributor_name: DIGIKEY; Distributor_part_number: 490-13248-1-ND; Footprint Path: Y:\MIS_DATABASE\Library\ALTIUM_TOOL\PCB_FOOTPRINTS\Altium_Footprint_Lib.PcbLib; Height: 1.00MM; Library Path: Y:\MIS_DATABASE\Library\ALTIUM_TOOL\SCHEMATICS_PARTS\MS_DISCRETE_Library.schlib; Mfr_name: MURATA; Mfr_part_number: GRM188R6YA106MA73D; Mistral Part No: 120019050016-R; Package: 0603; Part_type: CAPACITORS\CERAMIC; Project: BRUKER_SD820_COMMONDO; RoHS: RoHS; Temperature: -55°C+85°C; Tolerance: 20%; Voltage: 35V; Wattage: NA; Weight: 9mg; Datasheet: Y:\MIS_DATABASE\DATASHEETS\CAPACITORS\GRM188R6YA106MA73.PDF
C398 = CAP_POL: CAP TANTALUM 150uF 10V 10% ESR 600mE D7343; Chkd/date: ALVY/200921; Crtd /date: MANIRAJA/200921; Custom_Duty: 15%; Customs_HS_Code: 85322990; Distributor_name: DIGIKEY; Distributor_part_number: 718-1960-1-ND; Footprint Path: Y:\MIS_DATABASE\Library\ALTIUM_TOOL\PCB_FOOTPRINTS\Altium_Footprint_Lib.PcbLib; Height: 3.10MM; Library Path: Y:\MIS_DATABASE\Library\ALTIUM_TOOL\SCHEMATICS_PARTS\MS_DISCRETE_Library.schlib; Mfr_name: VISHAY; Mfr_part_number: 293D157X9010D2TE3; Mistral Part No: 120021090007-R; Package: D7343; Part_type: CAPACITORS\TANTALUM; Project: TI_AM62x SKEVM_BRD; RoHS: RoHS; Temperature: -55°C+125°C; Tolerance: 10%; Voltage: 10V; Wattage: NA; Weight: 400mg; Datasheet: Y:\MIS_DATABASE\DATASHEETS\CAPACITORS\293D_SER_MAR20.PDF
C399 = CAP: CAP CERAMIC 1000pF 2KV 10% X7R 1206; Chkd/date: SHREESHAIL/291106; Crtd /date: MAZHAR/281106; Custom_Duty: 15%; Customs_HS_Code: 85322990; Distributor_name: DIGIKEY; Distributor_part_number: 478-2956-1-ND; Footprint Path: Y:\MIS_DATABASE\Library\ALTIUM_TOOL\PCB_FOOTPRINTS\Altium_Footprint_Lib.PcbLib; Height: 1.52MM; Library Path: Y:\MIS_DATABASE\Library\ALTIUM_TOOL\SCHEMATICS_PARTS\MS_DISCRETE_Library.schlib; Mfr_name: AVX CORPORATION; Mfr_part_number: 1206GC102KAT1A; Mistral Part No: 120015080006-R; Package: 1206; Part_type: CAPACITORS\CERAMIC; Project: ADR1B; RoHS: RoHS; Temperature: -55°C+125°C; Tolerance: 10%; Voltage: 2KV; Wattage: NA; Weight: 16.2mg; Datasheet: Y:\MIS_DATABASE\DATASHEETS\CAPACITORS\AVX_HV-MLC.PDF
D1 D2 = DIODE_ZENER_SOT23_13: DIODE ZENER 250mW 6.8V SOT23-123; Chkd/date: MANIRAJA/031017; Crtd /date: MANIRAJA/031017; Custom_Duty: 15%; Customs_HS_Code: 85412900; Distributor_name: DIGIKEY; Distributor_part_number: BZX84C6V8LT1GOSCT-ND; Height: 1.11MM; Mfr_name: ON SEMICONDUCTOR; Mistral Part No: 130017100002-R; Package: SOT23-123; Part_type: DIODE\ZENER; Project: TI_MAXIE_CPB; RoHS: RoHS; Temperature: -65°C+150°C; Tolerance: NA; Voltage: 6.8V; Wattage: NA; Weight: 8mg; Datasheet: Y:\MIS_DATABASE\DATASHEETS\DISCRETES\DIODES\BZX84XX.PDF
J7 = CON_USB-A_4_2SH: CON USB-A TYPE 4POS FEMALE RT SMD; Chkd/date: MANIRAJA/271017; Crtd /date: MANIRAJA/271017; Custom_Duty: 24%; Customs_HS_Code: 85369090; Distributor_name: DIGIKEY; Distributor_part_number: 732-5969-1-ND; Height: 7.35MM; Manufacturer: WURTH ELECTRONICS; Mfr_name: WURTH ELECTRONICS; Mfr_part_number: 629104151021; Mistral Part No: 150017100042-R; Package: SMD; Part_type: CONNECTOR\USB; Project: TI_SVB_MAXWELL_SPM; RoHS: RoHS; Temperature: -40°C+85°C; Tolerance: NA; Voltage: NA; Wattage: NA; Weight: NA; Datasheet: Y:\MIS_DATABASE\DATASHEETS\CONNECTORS\629104151021.PDF
L4 = INDUCTOR_DLW31S: IND COMMON MODE CHOKE 90E 280mA SMD; Chkd/date: MANIRAJA/270619; Crtd /date: MANIRAJA/270619; Custom_Duty: 24%; Customs_HS_Code: 85437099; Distributor_name: NA; Distributor_part_number: NA; Footprint Path: Y:\MIS_DATABASE\Library\ALTIUM_TOOL\PCB_FOOTPRINTS\Altium_Footprint_Lib.PcbLib; Height: 1.40MM; Library Path: Y:\MIS_DATABASE\Library\ALTIUM_TOOL\SCHEMATICS_PARTS\MS_DISCRETE_Library.schlib; Mfr_name: MURATA; Mfr_part_number: DLW21SZ900HQ2B; Mistral Part No: 130019060035-R; Package: SMD; Part_type: INDUCTOR; Project: TI_J7ES_CP; RoHS: RoHS; Temperature: -40°C+105°C; Tolerance: NA; Voltage: NA; Wattage: NA; Weight: 11mg; Datasheet: Y:\MIS_DATABASE\DATASHEETS\DISCRETES\INDUCTORS\DLW21SZ900HQ2B.PDF
R124 R134 = RESISTOR: RES 16.5K 1/16W 1% 0402; Chkd/date: ALVY/091220; Crtd /date: MANIRAJA/091220; Custom_Duty: 15%; Customs_HS_Code: 85332119; Distributor_name: DIGIKEY; Distributor_part_number: YAG3002CT-ND; Footprint Path: Y:\MIS_DATABASE\Library\ALTIUM_TOOL\PCB_FOOTPRINTS\Altium_Footprint_Lib.PcbLib; Height: 0.40MM; Library Path: Y:\MIS_DATABASE\Library\ALTIUM_TOOL\SCHEMATICS_PARTS\MS_DISCRETE_Library.schlib; Mfr_name: YAGEO AMERICA; Mfr_part_number: RC0402FR-0716K5L; Mistral Part No: 110020120011-R; Package: 0402; Part_type: RESISTORS\FIXED; Project: TI_AM243x LP EVM; RoHS: RoHS; Temperature: -55°C+155°C; Tolerance: 1%; Voltage: NA; Wattage: 1/16W; Weight: 0.65mg; Datasheet: Y:\MIS_DATABASE\DATASHEETS\RESISTORS\RCXXXXL-SER_MAR18.PDF
R125 R135 = RESISTOR: RES 3.4K 1/20W 1% 0201; Chkd/date: VASANTHA/250116; Crtd /date: VASANTHA/250116; Custom_Duty: 15%; Customs_HS_Code: 85332119; Distributor_name: DIGIKEY; Distributor_part_number: ERJ-1GNF3401C-ND; Footprint Path: Y:\MIS_DATABASE\Library\ALTIUM_TOOL\PCB_FOOTPRINTS\Altium_Footprint_Lib.PcbLib; Height: 0.26MM; Library Path: Y:\MIS_DATABASE\Library\ALTIUM_TOOL\SCHEMATICS_PARTS\MS_DISCRETE_Library.schlib; Mfr_name: PANASONIC-ECG; Mfr_part_number: ERJ-1GNF3401C; Mistral Part No: 110016010003-R; Package: 0201; Part_type: RESISTORS\FIXED; Project: QUADIO; RoHS: RoHS; Temperature: -55°C+125°C; Tolerance: 1%; Voltage: NA; Wattage: 1/20W; Weight: 0.15mg; Datasheet: Y:\MIS_DATABASE\DATASHEETS\RESISTORS\PAN-ERJSER_NOV17.PDF
R331 R344 = RESISTOR: RES 499E 1/16W 0.1% 0402; Chkd/date: ALVY/200921; Crtd /date: MANIRAJA/200921; Custom_Duty: 15%; Customs_HS_Code: 85332119; Distributor_name: DIGIKEY; Distributor_part_number: YAG1440CT-ND; Footprint Path: Y:\MIS_DATABASE\Library\ALTIUM_TOOL\PCB_FOOTPRINTS\Altium_Footprint_Lib.PcbLib; Height: 0.35MM; Library Path: Y:\MIS_DATABASE\Library\ALTIUM_TOOL\SCHEMATICS_PARTS\MS_DISCRETE_Library.schlib; Mfr_name: YAGEO AMERICA; Mfr_part_number: RT0402BRD07499RL; Mistral Part No: 110021020006-R; Package: 0402; Part_type: RESISTORS\FIXED; Project: TI_AM62x SKEVM_BRD; RoHS: RoHS; Temperature: -55°C+155°C; Tolerance: 0.1%; Voltage: NA; Wattage: 1/16W; Weight: 0.65mg; Datasheet: Y:\MIS_DATABASE\DATASHEETS\RESISTORS\YAGEO_RT-SERIES.PDF
R338 R345 = RESISTOR: RES 10K 1/20W 1% 0201; Chkd/date: VASANTHA/270117; Crtd /date: MANIRAJA/270117; Custom_Duty: 15%; Customs_HS_Code: 85332119; Distributor_name: DIGIKEY; Distributor_part_number: 311-10.0KMCT-ND; Footprint Path: Y:\MIS_DATABASE\Library\ALTIUM_TOOL\PCB_FOOTPRINTS\Altium_Footprint_Lib.PcbLib; Height: 0.26MM; Library Path: Y:\MIS_DATABASE\Library\ALTIUM_TOOL\SCHEMATICS_PARTS\MS_DISCRETE_Library.schlib; Mfr_name: YAGEO AMERICA; Mfr_part_number: RC0201FR-0710KL; Mistral Part No: 110011040018-R; Package: 0201; Part_type: RESISTORS\FIXED; Project: GOLDEN-I LITE; RoHS: RoHS; Temperature: -55°C+125°C; Tolerance: 1%; Voltage: NA; Wattage: 1/20W; Weight: 0.17mg; Datasheet: Y:\MIS_DATABASE\DATASHEETS\RESISTORS\RCXXXXL-SER_MAR18.PDF
R389 = RESISTOR: RES 0E 1/10W 5% 0603; Chkd/date: MANIRAJA/051217; Crtd /date: BAVISH/180211; Custom_Duty: 15%; Customs_HS_Code: 85332119; Distributor_name: DIGIKEY; Distributor_part_number: 311-0.0GRCT-ND; Footprint Path: Y:\MIS_DATABASE\Library\ALTIUM_TOOL\PCB_FOOTPRINTS\Altium_Footprint_Lib.PcbLib; Height: 0.55MM; Library Path: Y:\MIS_DATABASE\Library\ALTIUM_TOOL\SCHEMATICS_PARTS\MS_DISCRETE_Library.schlib; Manufacturer: YAGEO AMERICA; Mfr_name: PANASONIC-ECG; Mfr_part_number: RC0603JR-070RL; Mistral Part No: 110011020013-R; Package: 0603; Part_type: RESISTORS\FIXED; Project: KENNEL; RoHS: RoHS; Temperature: -55°C+155°C; Tolerance: 5%; Voltage: NA; Wattage: 1/10W; Weight: 2mg; Datasheet: Y:\MIS_DATABASE\DATASHEETS\RESISTORS\RCXXXXL-SER_MAR18.PDF
U30 = TPD3S014D_SOT23-6: IC ESD PROTECTION FOR AUTO USB PORT WITH CURRENT LIMIT SWITCH SOT23-6; Chkd/date: MANIRAJA/180918; Crtd /date: ALVY/180918; Custom_Duty: 15%; Customs_HS_Code: 85423100; Distributor_name: DIGIKEY; Distributor_part_number: 296-44163-1-ND; Footprint Path: Y:\MIS_DATABASE\Library\ALTIUM_TOOL\PCB_FOOTPRINTS\Altium_Footprint_Lib.PcbLib; Height: 1.45MM; Library Path: Y:\MIS_DATABASE\Library\ALTIUM_TOOL\SCHEMATICS_PARTS\MS_MISCINTERFACE_Library.schlib; Mfr_name: TEXAS INSTRUMENTS; Mfr_part_number: TPD3S014TDBVRQ1; Mistral Part No: 141018090014-R; Package: SOT23-6; Part_type: ICS\INTERFACE; Project: TI_J7ES_EVM_CP; RoHS: RoHS; Temperature: -40°C+105°C; Tolerance: NA; Voltage: NA; Wattage: NA; Weight: NA; Datasheet: Y:\MIS_DATABASE\DATASHEETS\ICS\INTERFACE\TPD3S014-Q1.PDF

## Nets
DGND: C22.2 C25.1 C33.1 C36.1 C95.2 C96.2 C102.2 C103.1 C179.2 C181.2 C182.2 C184.2 C185.1 C186.2 C189.1 C190.2 C398.2 C399.2 C400.2 C401.1 C530.1 D1.1(A) D2.1(A) J3.6 J3.9 J3.14 J3.20 J3.25 J3.34 J7.4(GND) J8.2 J8.3 J8.7 J8.9 J8.14 J8.15 J8.20 J8.27 R77.1 R141.2 R144.1 R271.1 R286.1 R331.2 R338.2 R344.2 R345.2 R389.2 U10.4(GND) U30.2(GND) U33.8(GND) U53.B1(GND) U57.B1(GND) U124.3(GND) Y1.2 Y1.4 ; also on sheet 9 10 11 12 13 14 15 16 17 18 19 20 21 22 23 24 25 26 27 28 29 30 31 35 36 37 38 39 40 41 42 43
VBUS_5V0_TYPEA: C96.1 C398.1 J7.1(VCC) R125.2 U30.4(OUT)
VBUS_TYPEC2: R135.2 ; also on sheet 9 35
VCC1V8_SYS: C22.1 R40.1 U10.1(VCCA) ; also on sheet 12 13 17 18 20 36 38 39 41
VCC3V3_EXP: C184.1 C189.2 C190.1 J3.1 J3.17 R287.1 R288.1 R289.1 R290.1 R291.1 U57.A1(VOUT) ; also on sheet 37
VCC5V0_EXP: C181.1 C185.2 C186.1 J3.2 J3.4 U53.A1(VOUT)
VCC_3V3_SYS: C25.2 C103.2 C182.1 C400.1 C401.2 C530.2 J8.1 R128.1 R388.1 R390.2 R391.1 R392.2 R465.2 U10.8(VCCB) U33.16(VCC) U57.A2(VIN) U124.5(VCC) ; also on sheet 9 10 12 13 17 18 19 21 22 23 25 26 28 29 30 35 36 37 38 39 40 41 42
VCC_5V0: C95.1 C102.1 C179.1 R270.1 R281.2 U30.3(IN) U53.A2(VIN) ; also on sheet 9 10 23 37 40
AUDIO_EXT_REFCLK1: R55.1 ; also on sheet 40
CAN_FD_WKUP_HDR_INH: J8.5 R75.1
CAN_FD_WKUP_SW_INH: R82.2 ; also on sheet 43
CAN_IO_3V3: R65.1 R579.2 ; also on sheet 12 14 30 43
CONN_MCU_PORz: J8.28 R465.1 ; also on sheet 41
CONN_MCU_RESETz: J8.25 R390.1 ; also on sheet 42
CPSW_ETH2_INH: U124.2(IN_A) ; also on sheet 23
ETH_CAN_INH: R70.1 R73.2 R75.2 R76.2 R82.1
ETH_CAN_INH_PREREG: R76.1 ; also on sheet 11
ETH_CAN_INH_SOC: R65.2 R73.1 R88.1
EXP_CLKOUT0: J3.7 ; also on sheet 41
EXP_EHRPWM1_B: J3.33 U18.B20(MCASP0_AXR0)
EXP_GPIO0_14: J3.22 U10.7(B1)
EXP_GPIO0_14_LT: U10.2(A1) ; also on sheet 20
EXP_GPIO0_32: J3.30 ; also on sheet 31
EXP_GPIO0_33: J3.31 ; also on sheet 31
EXP_GPIO0_36: J3.29 ; also on sheet 31
EXP_GPIO0_38: J3.16 ; also on sheet 31
EXP_GPIO0_39: J3.18 ; also on sheet 31
EXP_GPIO0_40/PR0_ECAP0_IN_APWM_OUT: J3.32 ; also on sheet 31
EXP_GPIO0_41: J3.37 ; also on sheet 31
EXP_GPIO0_42: J3.13 ; also on sheet 31
EXP_GPIO1_22: J3.15 ; also on sheet 41
EXP_HAT_DETECT: J3.39 ; also on sheet 39
EXP_I2C2_SCL: J3.5 ; also on sheet 37
EXP_I2C2_SDA: J3.3 ; also on sheet 37
EXP_PS_3V3_EN: R286.2 U57.B2(ON) ; also on sheet 39
EXP_PS_5V0_EN: R271.2 U53.C2(ON) ; also on sheet 39
EXP_SPI0_CLK: J3.23 ; also on sheet 41
EXP_SPI0_CS0: J3.24 R290.2 ; also on sheet 41
EXP_SPI0_CS1: J3.26 R289.2 ; also on sheet 41
EXP_SPI0_D0: J3.19 ; also on sheet 41
EXP_SPI0_D1: J3.21 ; also on sheet 41
EXP_SPI2_CLK: J3.12 ; also on sheet 36
EXP_SPI2_CS0/EHRPWM0_A: J3.35 R287.2 ; also on sheet 36
EXP_SPI2_CS1: J3.11 R288.2 U18.A19(MCASP0_ACLKX)
EXP_SPI2_CS2: J3.36 R291.2 U18.B18(MCASP0_AXR1)
EXP_SPI2_D0: J3.40 ; also on sheet 36
EXP_SPI2_D1/ECAP2_IN_APWM_OUT: J3.38 ; also on sheet 36
EXP_UART5_RXD: J3.10 ; also on sheet 41
EXP_UART5_TXD: J3.8 ; also on sheet 41
GPIO_MCU_SoC_INTn: R573.1 U18.B9(MCU_MCAN1_RX) ; also on sheet 42
MCU_GPIO0_15: J8.10 R89.2
MCU_GPIO0_15_R: R88.2 R89.1 U18.D7(MCU_MCAN1_TX)
MCU_GPIO0_16: J8.11 R573.2
MCU_I2C0_SCL: J8.24 R388.2 U18.E12(MCU_I2C0_SCL) ; also on sheet 12
MCU_I2C0_SDA: J8.21 R391.2 U18.D9(MCU_I2C0_SDA) ; also on sheet 12
MCU_INTn: U18.E11(MCU_SPI0_CS0) ; also on sheet 12
MCU_MCAN0_RX: J8.22 U18.E8(MCU_MCAN0_RX)
MCU_MCAN0_TX: J8.16 U18.C7(MCU_MCAN0_TX)
MCU_OSC0_XI: R69.2 R71.2 U18.A12(MCU_OSC0_XI)
MCU_OSC0_XO: R74.2 R77.2 U18.A11(MCU_OSC0_XO)
MCU_RESETSTATz: J8.23 TP45.1(TP) ; also on sheet 41
MCU_SAFETY_ERRORz_1V8: TP9.1(TP) U10.3(A2) ; also on sheet 41
MCU_SAFETY_ERRORz_3V3: J8.26 U10.6(B2) ; also on sheet 12
MCU_SPI0_CLK: J8.18 U18.B13(MCU_SPI0_CLK)
MCU_SPI0_CS1: J8.8 R580.1
MCU_SPI0_CS1_R: R580.2 R581.2 U18.C11(MCU_SPI0_CS1)
MCU_SPI0_D0: J8.6 U18.A15(MCU_SPI0_D0)
MCU_SPI0_D1: J8.4 U18.B12(MCU_SPI0_D1)
MCU_UART0_CTS: U18.B11(MCU_UART0_CTSN) U33.9(3A)
MCU_UART0_CTS_3V3: U33.11(3B1) ; also on sheet 30
MCU_UART0_CTS_CONN: J8.12 U33.10(3B2)
MCU_UART0_MUX_OE: R141.1 U33.15(~{OE})
MCU_UART0_MUX_SEL: J10.2 R144.2 U33.1(S)
MCU_UART0_RTS: U18.D10(MCU_UART0_RTSN) U33.12(4A)
MCU_UART0_RTS_3V3: U33.14(4B1) ; also on sheet 30
MCU_UART0_RTS_CONN: J8.17 U33.13(4B2)
MCU_UART0_RX_3V3: U33.2(1B1) ; also on sheet 30
MCU_UART0_RXD: U18.D8(MCU_UART0_RXD) U33.4(1A)
MCU_UART0_RXD_CONN: J8.13 U33.3(1B2)
MCU_UART0_TX_3V3: U33.5(2B1) ; also on sheet 30
MCU_UART0_TXD: U18.F8(MCU_UART0_TXD) U33.7(2A)
MCU_UART0_TXD_CONN: J8.19 U33.6(2B2)
REFCLK1_R: R55.2 U18.A20(MCASP0_AFSX)
RMII_PHY_OBSCLK: R581.1 ; also on sheet 23
SoC_CLKIN: R69.1 ; also on sheet 24
SoC_I2C0_SCL: J3.28 ; also on sheet 9 12 21 23 41
SoC_I2C0_SDA: J3.27 ; also on sheet 9 12 21 23 41
SOC_SPI2_CLK: U18.A21(MCASP0_ACLKR) ; also on sheet 36
SOC_SPI2_CS0: U18.B21(MCASP0_AFSR) ; also on sheet 36
SOC_SPI2_D0: U18.C19(MCASP0_AXR3) ; also on sheet 36
SOC_SPI2_D1: U18.B19(MCASP0_AXR2) ; also on sheet 36
SoC_USB0_DM: U18.AA10(USB0_DM) ; also on sheet 35
SoC_USB0_DP: U18.AA9(USB0_DP) ; also on sheet 35
SoC_USB0_DRVVBUS: U18.C20(USB0_DRVVBUS) ; also on sheet 9
SoC_USB0_RCALIB: R331.1 U18.W10(USB0_RCALIB)
SoC_USB0_VBUS: R134.1 R338.1 U18.V8(USB0_VBUS)
SoC_USB1_DM: L4.1(IN1) U18.Y11(USB1_DM)
SoC_USB1_DP: L4.4(OUT2) U18.Y10(USB1_DP)
SoC_USB1_DRVVBUS: R128.2 R130.1 U18.D19(USB1_DRVVBUS)
SoC_USB1_RCALIB: R344.1 U18.U7(USB1_RCALIB)
SoC_USB1_VBUS: R124.1 R345.1 U18.V6(USB1_VBUS)
USB_TYPEA_EARTH: C399.1 J7.SH1 J7.SH2 R389.1
USB_TYPEACONN_DM: J7.2(D-) L4.2(IN2) U30.5(D1)
USB_TYPEACONN_DP: J7.3(D+) L4.3(OUT1) U30.6(D2)
N16906426: C33.2 R71.1 Y1.1
N16906432: C36.2 R74.1 Y1.3
N16931396: R270.2 U53.B2(CL)
N16931420: R281.1 U53.C1(OC)
N17492093: R40.2 U10.5(OE)
N17492111: J10.1 R392.1
N17726648: D2.3(C) R134.2 R135.1
N20199452: D1.3(C) R124.2 R125.1
N21068099: R130.2 U30.1(EN)
N23823404: R70.2 R579.1 U124.4(OUT)

Not connected (* = marked no-connect by the designer): D1 2(NC)*; D2 2(NC)*; U124 1(NC)*

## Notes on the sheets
sheet 32
- USER EXPANSION CONNECTOR
- GPIO1_10
- GPIO1_9
- GPIO1_7
- GPIO1_8
- GPIO1_14
- Note: Expansion boards should take care
  of the null modem connectivity for the
  UART signals (cross-over of Rx and Tx)
- GPIO1_13
- R55(Series damping resistor) should be placed close to SoC
- SoC_I2C2_SCL
- SoC_I2C2_SDA
- GPIO0_43
- GPIO0_44
- GPIO1_30
- GPIO1_24
- GPIO1_25
- GPIO1_11
- GPIO1_14
- GPIO0_42
- GPIO1_22
- GPIO0_38
- GPIO1_18
- GPIO0_39
- GPIO1_19
- GPIO0_14
- GPIO1_17
- GPIO1_15
- GPIO1_16
- GPIO1_27
- GPIO1_26
- GPIO0_33
- GPIO0_36
- GPIO0_32
- GPIO0_40
- MCASP1_AXR2
- GPIO1_10
- PWM required as per RPi sheet
  NA in Pinmux
- GPIO1_13
- GPIO1_9
- GPIO0_41
- GPIO1_8
- GPIO1_7
- Silk: USER EXPN
- POWER SWITCHES FOR USER EXPANSION CONNECTOR
- NOTE:
- AM62A Starter Kit shall not be powered through the 5V0 or 3V3 pins on the 40-pin User Expansion
  Connector.
  User Expansion Connector I/O are not fail-safe and shall not be driven when AM62A Starter Kit is
  not powered.
  5V supply of User Expansion Connector is limited to sourcing 155mA max.
  3V3 supply of User Expansion Connector is limited to sourcing 500mA max.
- It should be connected to PORz of the SoC TBD
sheet 33
- SOC - MCU DOMAIN
- $:R69 TRI-PAD WITH R71
- Logic HIGH to LOW transition on this signal
  records a CANUART I/O Wakeup Event
- Note: R76, R73 are
  Tripad
- $:R74 TRI-PAD WITH R77
- MCU HEADER
- MCU_UART0 MUX
- Silk: MCU HDR
- INPUT/OUTPUT
- OEn
- SEL
- An
- L
- L(DEFAULT)
- An=nB1
- SOC - FT4232
- L
- H
- An=nB2
- SOC - MCU HEADER
sheet 34
- USB1 TYPE-A
- 90E
- To Type- C connector
- To Type- A connector
- 90E
- Silk: TYPE-A
- 90E
- Note: Recommended VBUS circuit for USB connector. Supports 5V-30V VBUS
- DLW21SZ900HQ2B
